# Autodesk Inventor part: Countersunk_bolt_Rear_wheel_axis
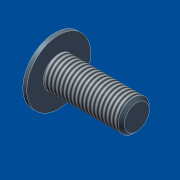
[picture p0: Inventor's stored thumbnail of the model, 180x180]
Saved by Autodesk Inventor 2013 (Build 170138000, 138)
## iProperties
Shininess: 41.0
Length Units: 11269
Angle Units: 11279
Time Units: 11290
Mass Units: 11283
Length Display Precision: 3
Angle Display Precision: 2
Created: 2001-04
Part Number: Countersunk_bolt_Rear_wheel_axis
Material: Standard
Document SubType Name: Modellieren
Designer: dl
Density: 1 g/cm^3
Density: 0.0
Volumn: 0.0
Area: 0.0
PropertySet Name: Model Information
Control State: 0
Master: False
Checked Out: False
Author: dl
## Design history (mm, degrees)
sketch "Sketch2"
  geometry: L1 (-1.443, 2.5)-(1.443, 2.5); L2 (1.443, 2.5)-(2.887, 0); L3 (2.887, 0)-(1.443, -2.5); L4 (1.443, -2.5)-(-1.443, -2.5); L5 (-1.443, -2.5)-(-2.887, 0); L6 (-2.887, 0)-(-1.443, 2.5); C1 r 3 at (0, 0) reference; C2 r 6.5 at (0, 0) reference
  constraints: 12 end point, 6 parallel, 1 horizontal
  dimensions: "d13" = 5 distance between parallel lines of L4 L1; "d14" = 5 distance between parallel lines of L3 L6 (= d13); "d16" = 5 distance between parallel lines of L2 L5 (= d13); "d17" = 120 deg angle of L5 L6; "d18" = 120 deg angle of L4 L5 (= d17); "d19" = 120 deg angle of L3 L2 (derived); "d20" = 0 vertical distance of C2.centre L5.end; "d21" = 2.5 distance from line of C1.centre L6 (= 0.5 x d13)
extrude "Extrusion1" cut sketch "Sketch2" distance "d22" = 3; taper "d23" = 0 deg
body "Solid1"
revolve "Revolution1" stored, may be unused: angle "d8" = 90 deg
thread "Thread1" dims "d9" = 10, "d10" = 0
chamfer "Chamfer1" distance "d11" = 0.8; stored, may be unused: second distance "d12" = 0.8, angle "d31" = 45 deg
sketch "Sketch3"
  geometry: C1 r 3 at (0, 0) reference; 1 further point
  constraints: 1 coincident
hole "Hole1" sketch "Sketch3" diameter "d24" = 5; stored, may be unused: countersink angle "d28" = 60 deg, drill point angle "d30" = 118 deg; dims "d25" = 6, "d26" = 4, "d27" = 2, "d29" = 3
sketch "Sketch1"
  geometry: L1 (-0.293, -3.004)-(-0.293, -0.004); L2 (2.707, 3.496)-(2.707, 5.196); L3 (2.707, 5.196)-(3.707, 5.196); L4 (3.707, 5.196)-(3.707, 0.996); L5 (3.707, 0.996)-(23.707, 0.996); L6 (23.707, 0.996)-(23.707, -3.004); L7 (23.707, -3.004)-(-0.293, -3.004); A1 r 5 centre (4.575, -1.142) between (2.707, 3.496) and (-0.293, -0.004)
  constraints: 14 end point, 5 parallel, 2 point on circle, 1 centre point, 1 perpendicular, 1 vertical
  dimensions: "d0" = 3 distance of L1.start L1.end; "d1" = 6.5 distance from line of L7 L2.start; "d2" = 8.2 distance between parallel lines of L7 L3; "d3" = 4 distance between parallel lines of L1 L4; "d4" = 1 distance of L2.end L3.end; "d5" = 5 radius of A1; "d6" = 20 distance of L4.end L5.end; "d7" = 4 distance of L5.end L6.end
